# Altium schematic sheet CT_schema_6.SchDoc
size 411 x 381 mm
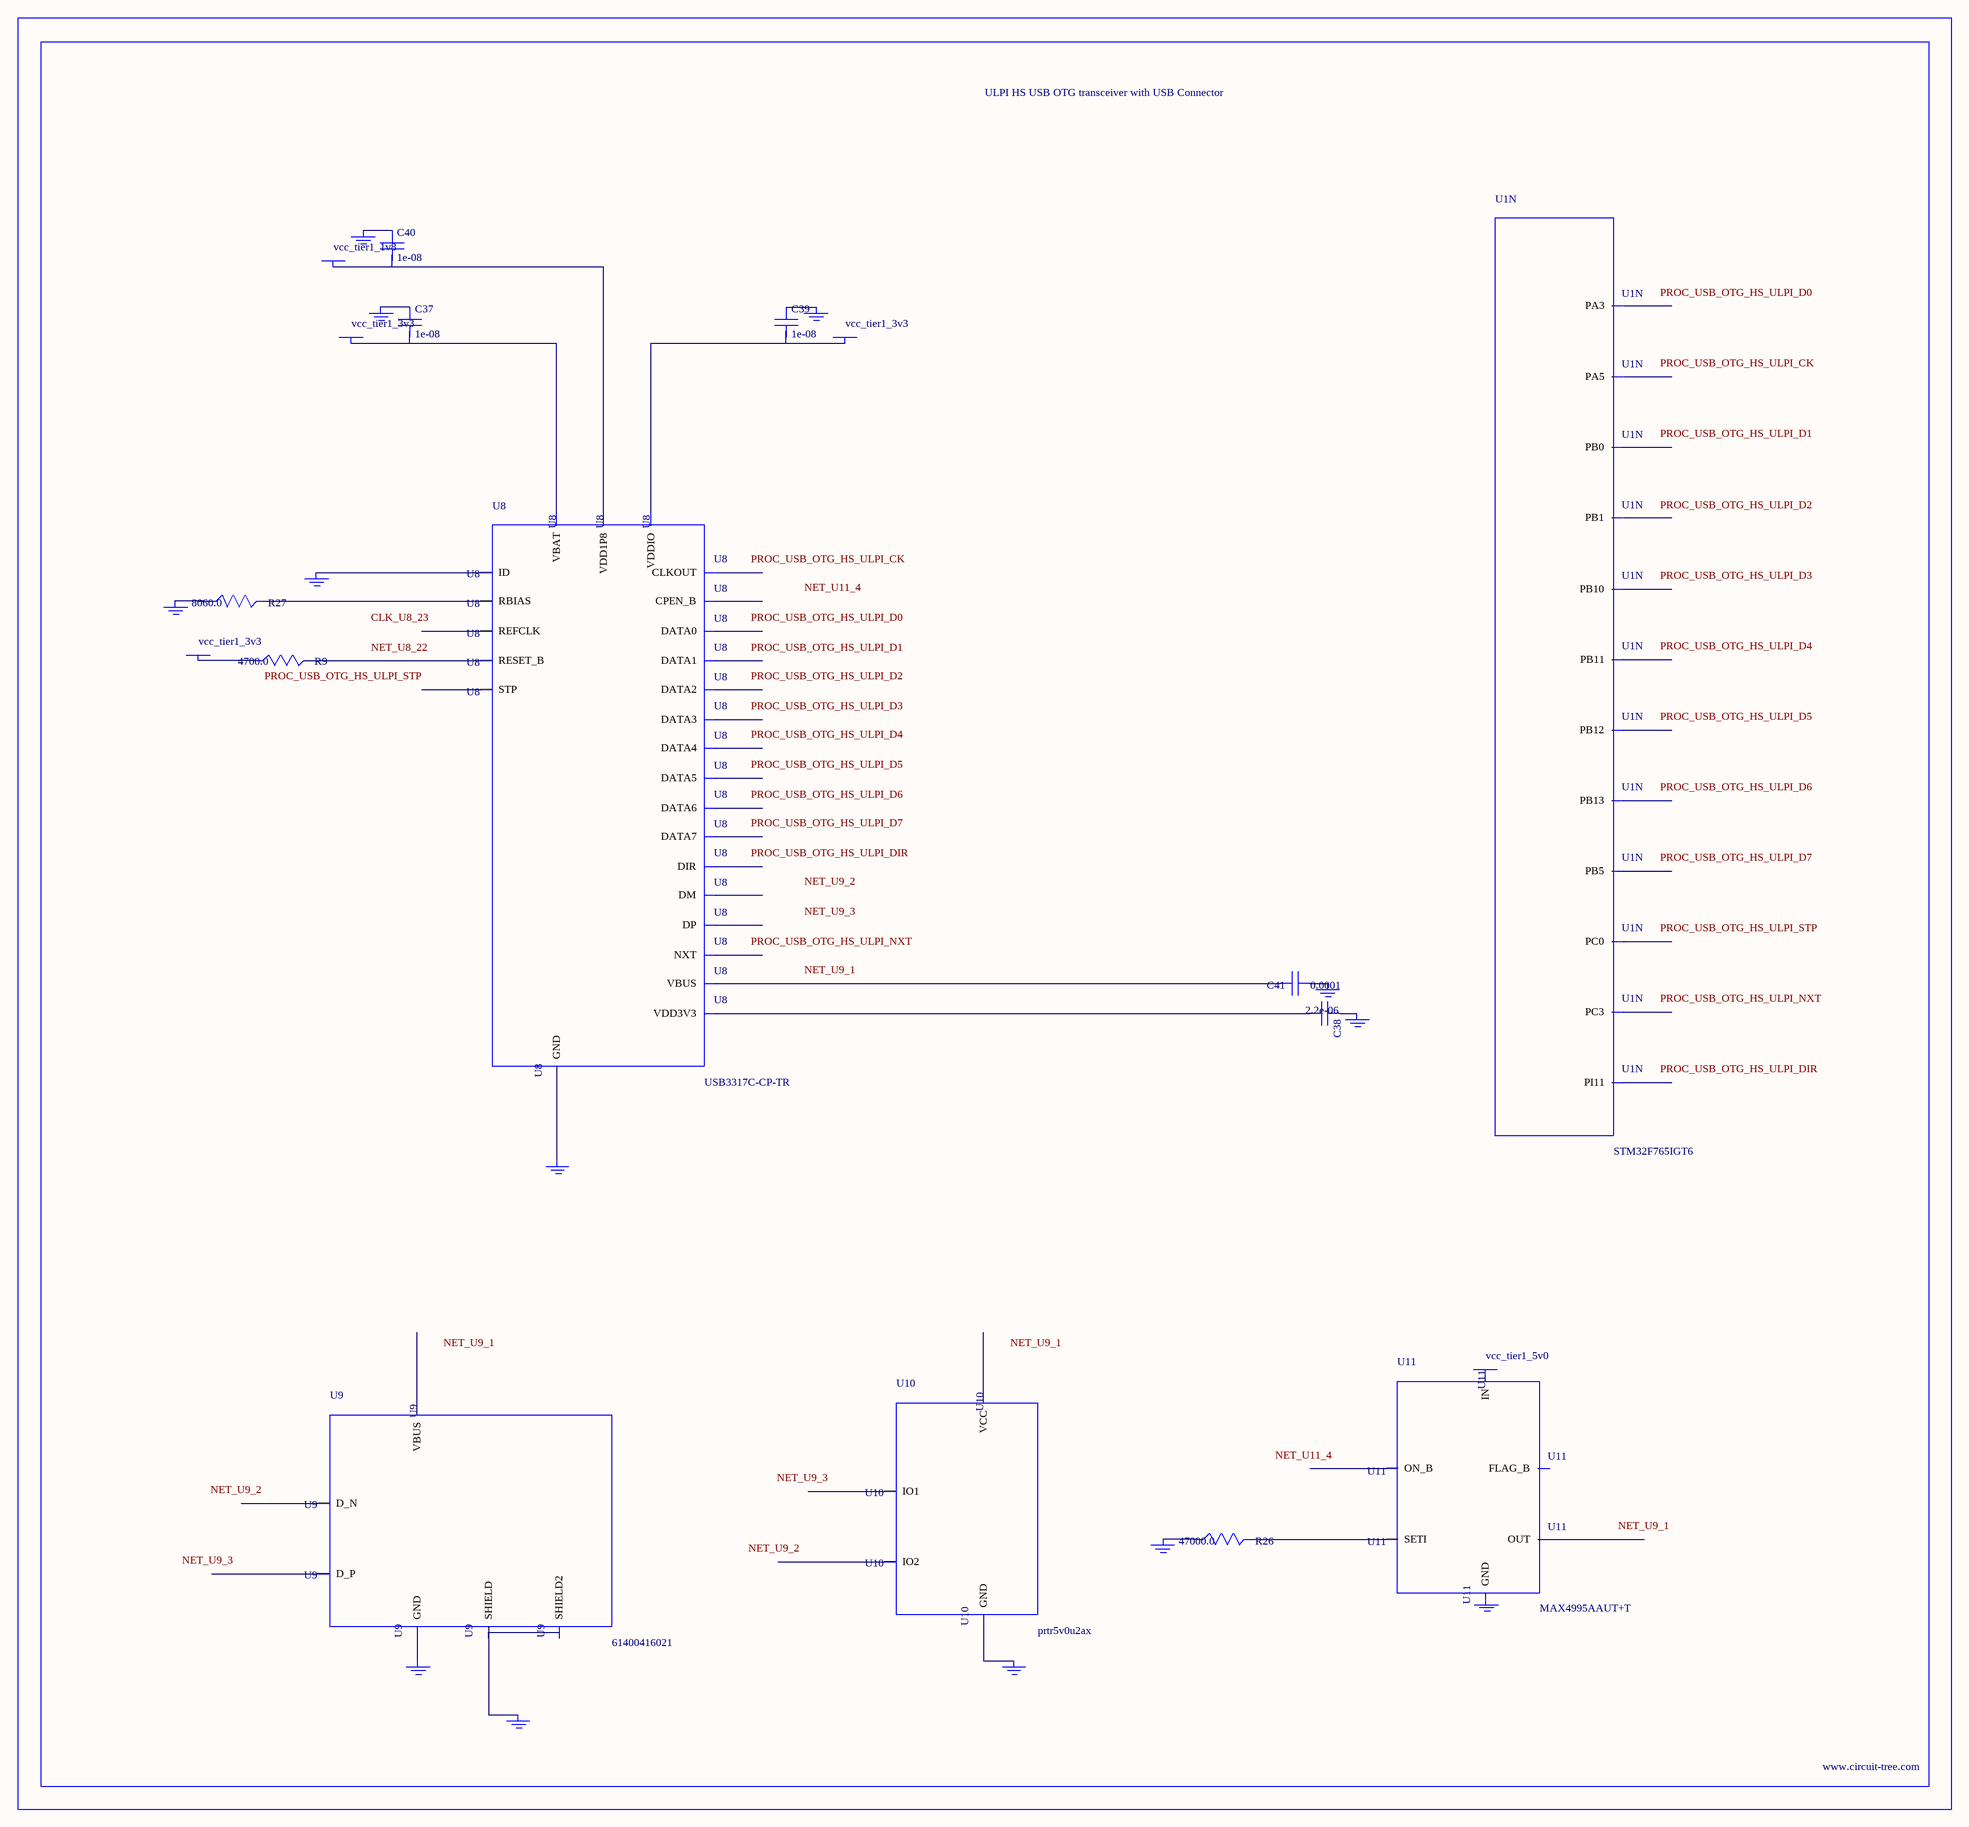
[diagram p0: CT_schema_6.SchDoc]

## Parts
BORDER5  (no value)
C37  1e-08  [C0402]
C38  2.2e-06  [C0603]
C39  1e-08  [C0402]
C40  1e-08  [C0402]
C41  0.0001  [R0603]
GND_INSTANCE_5_0  (no value)
GND_INSTANCE_5_1  (no value)
GND_INSTANCE_5_2  (no value)
GND_INSTANCE_5_3  (no value)
GND_INSTANCE_5_4  (no value)
GND_INSTANCE_5_5  (no value)
GND_INSTANCE_5_6  (no value)
GND_INSTANCE_5_7  (no value)
GND_INSTANCE_5_8  (no value)
GND_INSTANCE_5_9  (no value)
GND_INSTANCE_5_10  (no value)
GND_INSTANCE_5_11  (no value)
GND_INSTANCE_5_12  (no value)
POWER_INSTANCE_5_0  vcc_tier1_3v3
POWER_INSTANCE_5_1  vcc_tier1_3v3
POWER_INSTANCE_5_2  vcc_tier1_1v8
POWER_INSTANCE_5_3  vcc_tier1_3v3
POWER_INSTANCE_5_4  vcc_tier1_5v0
R9  4700.0  [R0603]
R26  47000.0  [R0603]
R27  8060.0  [R0603]
U1  STM32F765IGT6  [LQFP176]  (part N of 14)
U8  USB3317C-CP-TR  [QFN-24]
U9  61400416021  [USB-A-H]
U10  prtr5v0u2ax  [SOT143B]
U11  MAX4995AAUT+T  [SOT-23-6]

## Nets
NetC37_1: C37.1 GND_INSTANCE_5_2.0(GND)
NetC37_2: C37.2 POWER_INSTANCE_5_0.0(PWR) U8.3(VBAT)
NetC38_1: C38.1 GND_INSTANCE_5_3.0(GND)
NetC38_2: C38.2 U8.4(VDD3V3)
NetC39_1: C39.1 GND_INSTANCE_5_4.0(GND)
NetC39_2: C39.2 POWER_INSTANCE_5_1.0(PWR) U8.17(VDDIO)
NetC40_1: C40.1 GND_INSTANCE_5_5.0(GND)
NetC40_2: C40.2 POWER_INSTANCE_5_2.0(PWR) U8.21(VDD1P8)
NetC41_1: C41.1 GND_INSTANCE_5_1.0(GND)
NetC41_2: C41.2 U8.2(VBUS)
NetGND_INSTANCE_5_0_0: GND_INSTANCE_5_0.0(GND) U8.1(ID)
NetGND_INSTANCE_5_6_0: GND_INSTANCE_5_6.0(GND) R27.1
NetGND_INSTANCE_5_7_0: GND_INSTANCE_5_7.0(GND) U8.25(GND)
NetGND_INSTANCE_5_8_0: GND_INSTANCE_5_8.0(GND) U9.5(SHIELD) U9.6(SHIELD2)
NetGND_INSTANCE_5_9_0: GND_INSTANCE_5_9.0(GND) U9.4(GND)
NetGND_INSTANCE_5_10_0: GND_INSTANCE_5_10.0(GND) U10.1(GND)
NetGND_INSTANCE_5_11_0: GND_INSTANCE_5_11.0(GND) R26.1
NetPOWER_INSTANCE_5_3_0: POWER_INSTANCE_5_3.0(PWR) R9.1
NetR9_2: R9.2 U8.22(RESET_B)
NetR26_2: R26.2 U11.3(SETI)
NetR27_2: R27.2 U8.24(RBIAS)

Not connected (* = marked no-connect by the designer): GND_INSTANCE_5_12 0(GND); POWER_INSTANCE_5_4 0(PWR); U1 13(PI11) 32(PC0) 35(PC3) 47(PA3) 51(PA5) 56(PB0) 57(PB1) 79(PB10) 80(PB11) 92(PB12) 93(PB13) 163(PB5); U8 5(DM) 6(DP) 7(CPEN_B) 8(DATA7) 9(DATA6) 10(DATA5) 11(DATA4) 12(CLKOUT) 13(DATA3) 14(DATA2) 15(DATA1) 16(DATA0) 18(NXT) 19(DIR) 20(STP) 23(REFCLK); U9 1(VBUS) 2(D_N) 3(D_P); U10 2(IO1) 3(IO2) 4(VCC); U11 1(OUT) 2(GND) 4(ON_B) 5(IN) 6(FLAG_B)

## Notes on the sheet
- Labels drawn without touching a wire or pin: CLK_U8_23, NET_U8_22, NET_U9_1, NET_U9_2, NET_U9_3, NET_U11_4, PROC_USB_OTG_HS_ULPI_CK, PROC_USB_OTG_HS_ULPI_D0, PROC_USB_OTG_HS_ULPI_D1, PROC_USB_OTG_HS_ULPI_D2, PROC_USB_OTG_HS_ULPI_D3, PROC_USB_OTG_HS_ULPI_D4, PROC_USB_OTG_HS_ULPI_D5, PROC_USB_OTG_HS_ULPI_D6, PROC_USB_OTG_HS_ULPI_D7, PROC_USB_OTG_HS_ULPI_DIR, PROC_USB_OTG_HS_ULPI_NXT, PROC_USB_OTG_HS_ULPI_STP

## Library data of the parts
BORDER5 = BORDER_PAGE5
C37 C39 C40 = C0402C103K3RAC
C38 = C0603C225K8RACTU
C41 = C41
GND_INSTANCE_5_0-GND_INSTANCE_5_12 = GND
POWER_INSTANCE_5_0-POWER_INSTANCE_5_4 = PWR
R9 = RC0603JR-074K7L
R26 = RC0603JR-0747KL
R27 = ERJ-3EKF8061V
